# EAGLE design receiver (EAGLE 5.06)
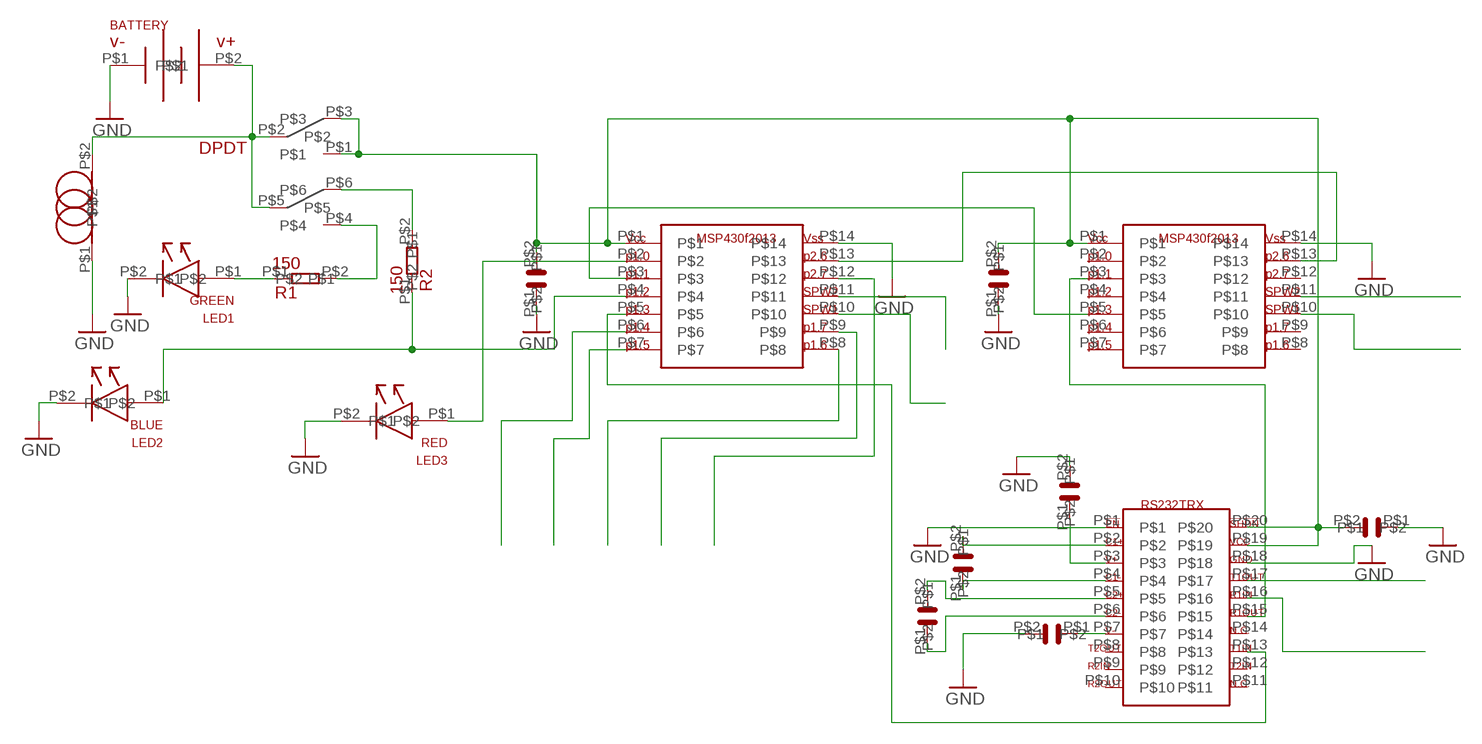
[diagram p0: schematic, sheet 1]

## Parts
BATTERY  1/2AA  [1/2AA]
C1  10uF  IND0603  [0603]
C2  1uF  CAP0402  [0402]
C3  1uF  CAP0402  [0402]
C4  100nF  CAP0402  [0402]
C5  100nF  CAP0402  [0402]
C6  100nF  CAP0402  [0402]
C7  100nF  CAP0402  [0402]
C8  100nF  CAP0402  [0402]
DPDT  DPDT  [DPDT]
LED1  GREEN  LEDREC  [LED]
LED2  BLUE  LEDREC  [LED]
LED3  RED  LEDREC  [LED]
MCU1  MSP430F2013  [TSSOP-14]
MCU2  MSP430F2013  [TSSOP-14]
R1  150  RES0402  [0402]
R2  150  RES0402  [0402]
RS232TRX  MAX3222  [TSSOP-20]

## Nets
GND: BATTERY.P$1 C1.P$1 C2.P$1 C3.P$1 C4.P$2 C7.P$2 C8.P$1 LED1.P$2 LED2.P$2 LED3.P$2 MCU1.P$14 MCU2.P$14 RS232TRX.P$1 RS232TRX.P$18
N$2: DPDT.P$4 R1.P$2
N$3: BATTERY.P$2 C1.P$2 DPDT.P$2 DPDT.P$5
N$5: C2.P$2 C3.P$2 C8.P$2 DPDT.P$1 DPDT.P$3 MCU1.P$1 MCU2.P$1 RS232TRX.P$19 RS232TRX.P$20
N$10: MCU1.P$11
N$11: MCU1.P$10
N$12: MCU2.P$11
N$14: MCU2.P$10
N$18: MCU1.P$3 MCU2.P$5
N$19: MCU1.P$13 MCU2.P$13
N$20: C5.P$2 RS232TRX.P$2
N$21: C5.P$1 RS232TRX.P$4
N$22: C4.P$1 RS232TRX.P$3
N$23: C7.P$1 RS232TRX.P$7
N$24: MCU2.P$3 RS232TRX.P$15
N$25: MCU1.P$5 RS232TRX.P$13
N$26: MCU1.P$6
N$27: C6.P$2 RS232TRX.P$5
N$28: C6.P$1 RS232TRX.P$6
N$29: RS232TRX.P$16
N$30: RS232TRX.P$17
N$31: MCU1.P$7
N$33: MCU1.P$8
N$34: MCU1.P$9
N$35: MCU1.P$12
N$36: LED2.P$1 MCU1.P$4 R2.P$1
N$37: LED3.P$1 MCU1.P$2
N$42: LED1.P$1 R1.P$1
N$43: DPDT.P$6 R2.P$2
Unconnected: MCU2.P$2 MCU2.P$4 MCU2.P$6 MCU2.P$7 MCU2.P$8 MCU2.P$9 MCU2.P$12 RS232TRX.P$8 RS232TRX.P$9 RS232TRX.P$10 RS232TRX.P$11 RS232TRX.P$12 RS232TRX.P$14

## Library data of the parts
BATTERY = my project parts:1/2AA
C1 = my project parts:IND0603
C2-C8 = my project parts:CAP0402
DPDT = my project parts:DPDT
LED1-LED3 = my project parts:LEDREC
MCU1 MCU2 = my project parts:MSP430F2013
R1 R2 = my project parts:RES0402
RS232TRX = my project parts:MAX3222

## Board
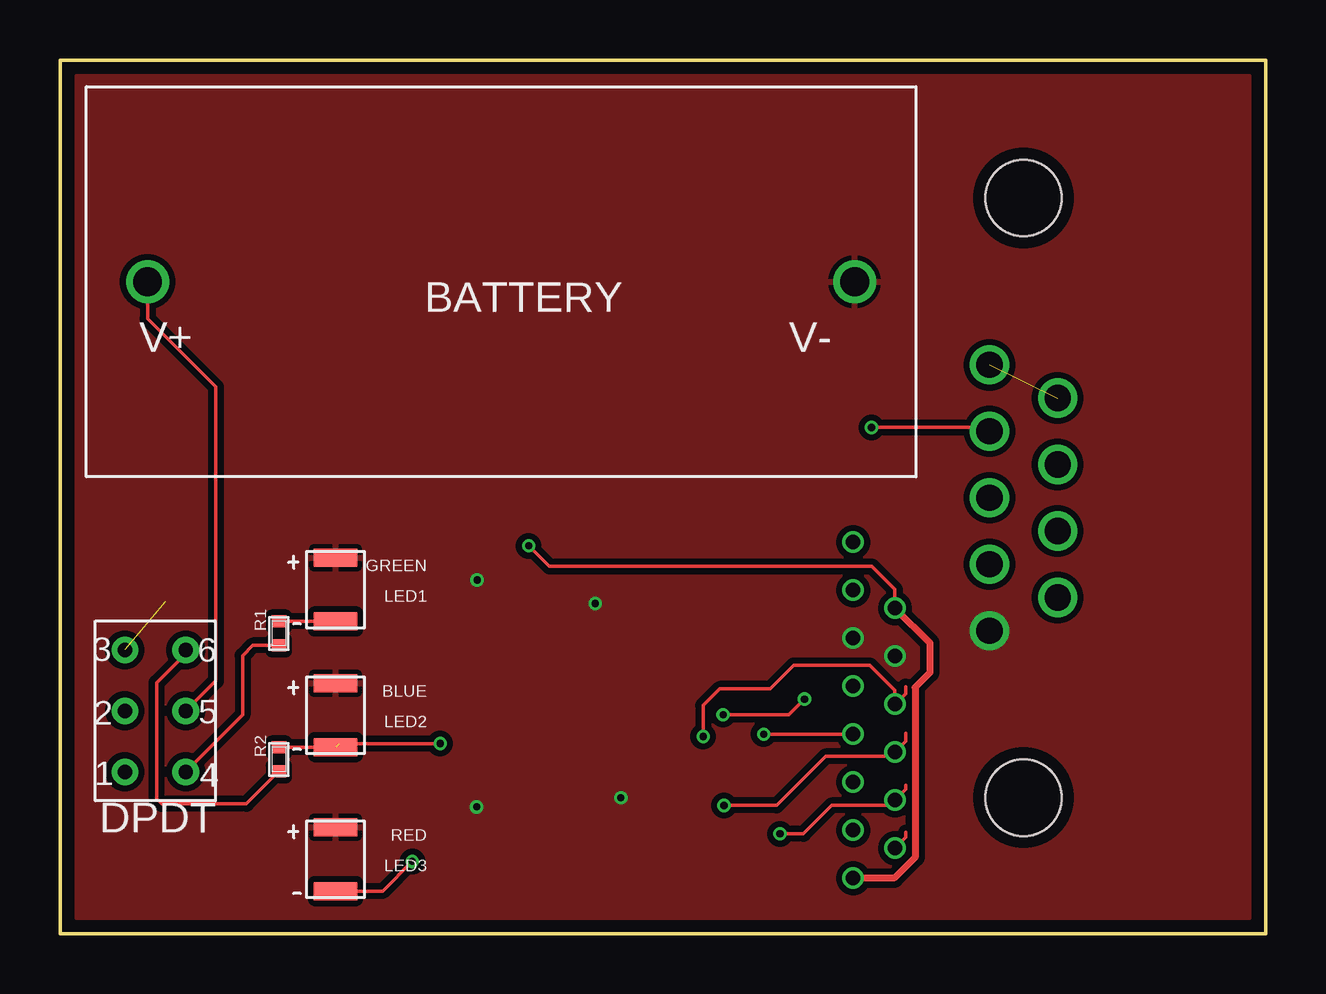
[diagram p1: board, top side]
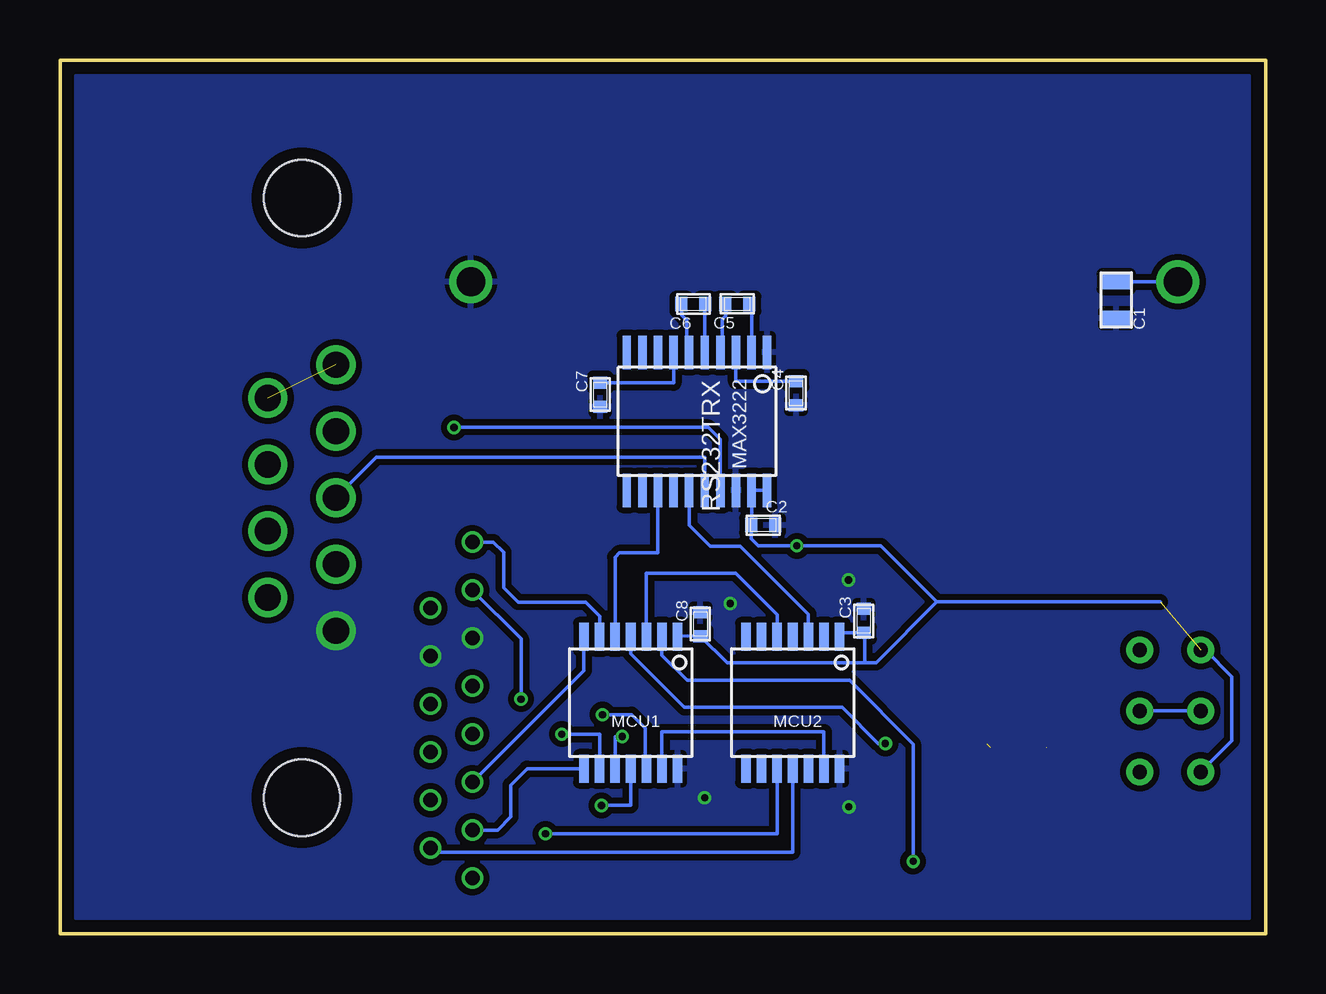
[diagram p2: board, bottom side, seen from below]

Size 50.23 x 36.4 mm. Coordinates in mm from the lower left corner, seen from the top.
Outline: 12.39,36.4 12.32,36.4
Outline: 12.31,36.4 11.81,36.4
Outline: 0,35.56 0,35.41
Outline: 0,35.87 0,35.17
Outline: 0,35.17 0,34.85
Outline: 2.31,0 2.36,0
Outline: 2.05,0 2.94,0
Outline: 2.94,0 3.53,0
Outline: 50.23,0.67 50.23,1.19
Outline: 50.23,1.19 50.23,1.3
Outline: 50.23,1 50.23,1.19
Outline: 50.23,1.19 50.23,1.87
Outline: 12.45,36.4 12.31,36.4
Outline: 12.31,36.4 0,36.4 0,35.17
Outline: 0,35.17 0,0 2.94,0
Outline: 2.94,0 50.23,0 50.23,1.19
Outline: 50.23,1.19 50.23,36.4 12.31,36.4
Copper layers (1*16): Top 0.035mm / dielectric 1.5mm / Bottom 0.035mm
Design rules "default *": minimum track width 0.15mm, minimum drill 0.3mm, track to track 6mil, track to pad 6mil, pad to pad 6mil, via to via 6mil, smd to smd 6mil, copper to edge 0.5mm, drill to drill 8mil, minimum pad ring 10mil, minimum via ring 5mil, stop-mask expansion 3mil, vias tented up to drill 12mil, thermal gap 0.2mm
Holes 3.18 mm at 40.15,5.66 40.15,30.65

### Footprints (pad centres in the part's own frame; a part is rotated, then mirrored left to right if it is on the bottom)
1/2AA = drill 1.194 round: P$1 -14.732,0; P$2 14.732,0
0603 = smd 0.629 x 1.138: P$1 -0.764,0; P$2 0.764,0
0402 = smd 0.5 x 0.6: P$1 -0.5,0; P$2 0.5,0
DPDT = drill 0.6 round: P$1 1.27,2.54; P$2 1.27,0; P$3 1.27,-2.54; P$4 -1.27,2.54; P$5 -1.27,0; P$6 -1.27,-2.54
LED = smd 1.8 x 0.75: P$1 0,1.325; P$2 0,-1.325
TSSOP-14 = smd 0.4 x 1.15: P$1 -1.95,-2.75; P$2 -1.3,-2.75; P$3 -0.65,-2.75; P$4 0,-2.75; P$5 0.65,-2.75; P$6 1.3,-2.75; P$7 1.95,-2.75; P$8 1.95,2.75; P$9 1.3,2.75; P$10 0.65,2.75; P$11 0,2.75; P$12 -0.65,2.75; P$13 -1.3,2.75; P$14 -1.95,2.75
TSSOP-20 = smd 1.4 x 0.35: P$1 -2.875,2.925; P$2 -2.875,2.275; P$3 -2.875,1.625; P$4 -2.875,0.975; P$5 -2.875,0.325; P$6 -2.875,-0.325; P$7 -2.875,-0.975; P$8 -2.875,-1.625; P$9 -2.875,-2.275; P$10 -2.875,-2.925; P$11 2.875,-2.925; P$12 2.875,-2.275; P$13 2.875,-1.625; P$14 2.875,-0.975; P$15 2.875,-0.325; P$16 2.875,0.325; P$17 2.875,0.975; P$18 2.875,1.625; P$19 2.875,2.275; P$20 2.875,2.925

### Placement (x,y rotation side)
BATTERY  18.38,27.16 180 top
C1  6.22,26.4 90 bottom
C2  20.93,17.02 180 bottom
C3  16.74,13.03 270 bottom
C4  19.56,22.52 270 bottom
C5  22.01,26.24 0 bottom
C6  23.84,26.23 0 bottom
C7  27.72,22.46 270 bottom
C8  23.55,12.9 270 bottom
DPDT  3.97,9.28 180 top
LED1  11.48,14.33 180 top
LED2  11.48,9.1 180 top
LED3  11.48,3.1 180 top
MCU1  26.45,9.62 180 bottom
MCU2  19.7,9.62 180 bottom
R1  9.12,12.51 270 top
R2  9.12,7.26 270 top
RS232TRX  23.69,21.34 270 bottom

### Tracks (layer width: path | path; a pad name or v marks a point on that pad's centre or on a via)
GND  (via drill 0.3, 0.6, 1.09)
  other vias: 33.05,12.31 34.79,11.56 23.37,5.66 22.3,13.75 17.36,5.28 17.38,14.73 38.73,12.62
  pour Bottom (isolate 0.254): 0.67,35.74 49.57,35.74 49.57,0.65 0.67,0.65
  pour Top (isolate 0.254): 0.67,35.74 49.57,35.74 49.57,0.65 0.67,0.65
N$2
  Top 0.15: R1.P$2 8.04,12.01 7.61,11.58 7.61,9.11 DPDT.P$4
N$3
  Top 0.15: BATTERY.P$2 3.65,25.62 6.21,23.06 6.49,22.78 6.49,10.53 DPDT.P$5
  Bottom 0.15: BATTERY.P$2 C1.P$2 | DPDT.P$5 DPDT.P$2
N$4  (via drill 1.09)
  other vias: 38.73,15.39
N$5  (via drill 0.3, 0.6)  (1 unrouted)
  Top 0.15: v19.53,16.16 20.39,15.3 33.83,15.3 34.79,14.34 v34.79,13.56
  Top 0.3: v33.05,2.31 34.76,2.31 35.63,3.18 35.63,10.26 36.24,10.87 36.24,12.11 v34.79,13.56
  Bottom 0.15: RS232TRX.P$20 RS232TRX.P$19 21.42,17.02 C2.P$2 21.42,16.45 21.13,16.16 v19.53,16.16 16.03,16.16 13.69,13.82 | MCU1.P$1 24.46,12.41 C8.P$2 22.43,11.29 16.69,11.29 | MCU2.P$1 17.75,12.54 C3.P$2 16.69,12.49 16.69,11.29 | 16.69,11.29 16.22,11.29 13.69,13.82 | 13.69,13.82 4.39,13.82 | DPDT.P$1 1.4,8.04 1.4,10.71 2.51,11.82 DPDT.P$3
N$6  (via drill 1.09)
  other vias: 41.57,14
N$7  (via drill 1.09)
  other vias: 41.57,16.77
N$8  (via drill 1.09)
  other vias: 41.57,19.54
N$10  (via drill 0.3, 0.6)
  Top 0.15: v27.67,5.34 29.86,5.34 31.9,7.38 34.61,7.38 v34.79,7.56 35.24,8.01 35.24,8.34
  Bottom 0.15: MCU1.P$11 26.45,5.34 v27.67,5.34
N$11  (via drill 0.3, 0.6)
  Top 0.15: v26.8,8.21 26.8,9.51 27.49,10.2 29.59,10.2 30.57,11.18 33.74,11.18 34.79,10.13 v34.79,9.56 35.23,10 35.23,10.29
  Bottom 0.15: MCU1.P$10 27.1,8.21 v26.8,8.21
N$12  (via drill 0.6)
  Top 0.15: v34.79,3.56 35.24,4.01 35.24,4.22
  Bottom 0.15: v34.79,3.56 34.63,3.4 19.7,3.4 MCU2.P$11
N$13  (via drill 0.6)
  other vias: 33.05,10.31
N$14  (via drill 0.3, 0.6)
  Top 0.15: v30,4.16 30.97,4.16 32.15,5.34 34.57,5.34 v34.79,5.56 35.24,6.01 35.24,6.18
  Bottom 0.15: MCU2.P$10 20.35,4.16 v30,4.16
N$18
  Bottom 0.15: MCU1.P$3 25.8,15.01 22.07,15.01 20.35,13.29 MCU2.P$5
N$19
  Bottom 0.15: MCU1.P$13 25.15,8.41 18.4,8.41 MCU2.P$13
N$20
  Bottom 0.15: RS232TRX.P$2 21.42,26.24 C5.P$2
N$21
  Bottom 0.15: RS232TRX.P$4 22.64,24.21 22.64,25.6 22.5,25.74 C5.P$1
N$22
  Bottom 0.15: RS232TRX.P$3 22.07,23.01 C4.P$1
N$23
  Bottom 0.15: RS232TRX.P$7 24.67,22.95 C7.P$1
N$24
  Bottom 0.15: MCU2.P$3 19.05,13.31 21.88,16.14 23.13,16.14 24.02,17.02 RS232TRX.P$15
N$25
  Bottom 0.15: RS232TRX.P$13 25.32,15.86 26.93,15.86 27.1,15.69 MCU1.P$5
N$26  (via drill 0.6)
  Bottom 0.15: v33.05,16.31 32.17,16.31 31.75,15.89 31.75,14.42 31.14,13.81 28.33,13.81 27.75,13.23 MCU1.P$6
N$27
  Bottom 0.15: C6.P$2 23.37,26.21 RS232TRX.P$5
N$28
  Bottom 0.15: RS232TRX.P$6 24.11,24.31 24.11,25.55 24.33,25.77 C6.P$1
N$29  (via drill 1.09)
  Bottom 0.15: RS232TRX.P$16 23.37,19.84 37.05,19.84 v38.73,18.16
N$30  (via drill 0.3, 1.09)
  Top 0.15: v33.81,21.09 38.57,21.09 v38.73,20.93
  Bottom 0.15: RS232TRX.P$17 22.72,20.59 23.21,21.09 v33.81,21.09
N$31  (via drill 0.6)
  Bottom 0.15: v33.05,6.31 28.4,10.96 MCU1.P$7
N$33  (via drill 0.6)
  Bottom 0.15: MCU1.P$8 30.77,6.87 31.45,6.19 31.45,4.86 32,4.31 v33.05,4.31
N$34  (via drill 0.3, 0.6)
  Top 0.15: v33.05,8.31 v29.32,8.31
  Bottom 0.15: v29.32,8.31 27.75,8.31 MCU1.P$9
N$35  (via drill 0.3, 0.6)
  Top 0.15: v27.63,9.12 30.37,9.12 v31.02,9.77
  Bottom 0.15: v27.63,9.12 26.41,9.12 25.84,8.55 25.84,6.91 MCU1.P$12 | v31.02,9.77 31.02,12.28 v33.05,14.31
N$36  (via drill 0.3)  (2 unrouted)
  Top 0.15: v15.84,7.92 11.63,7.92 | 11.48,7.76 LED2.P$1 9.14,7.77
  Bottom 0.15: MCU1.P$4 26.45,11.67 24.21,9.43 17.64,9.43 16.13,7.92 v15.84,7.92
N$37  (via drill 0.3)
  Top 0.15: LED3.P$1 13.45,1.77 v14.68,3.01
  Bottom 0.15: v14.68,3.01 14.68,7.9 17.33,10.55 24.1,10.55 25.15,11.6 MCU1.P$2
N$42
  Top 0.15: LED1.P$1 R1.P$1
N$43
  Top 0.15: DPDT.P$6 5.24,11.67 4.03,10.46 4.03,5.61 4.23,5.41 7.77,5.41 R2.P$2
N$221  (via drill 1.09)  (1 unrouted)
  other vias: 41.57,22.31 38.73,23.7

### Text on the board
tStop: CH1 | CH2 | RCV
bStop: RCP 2010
